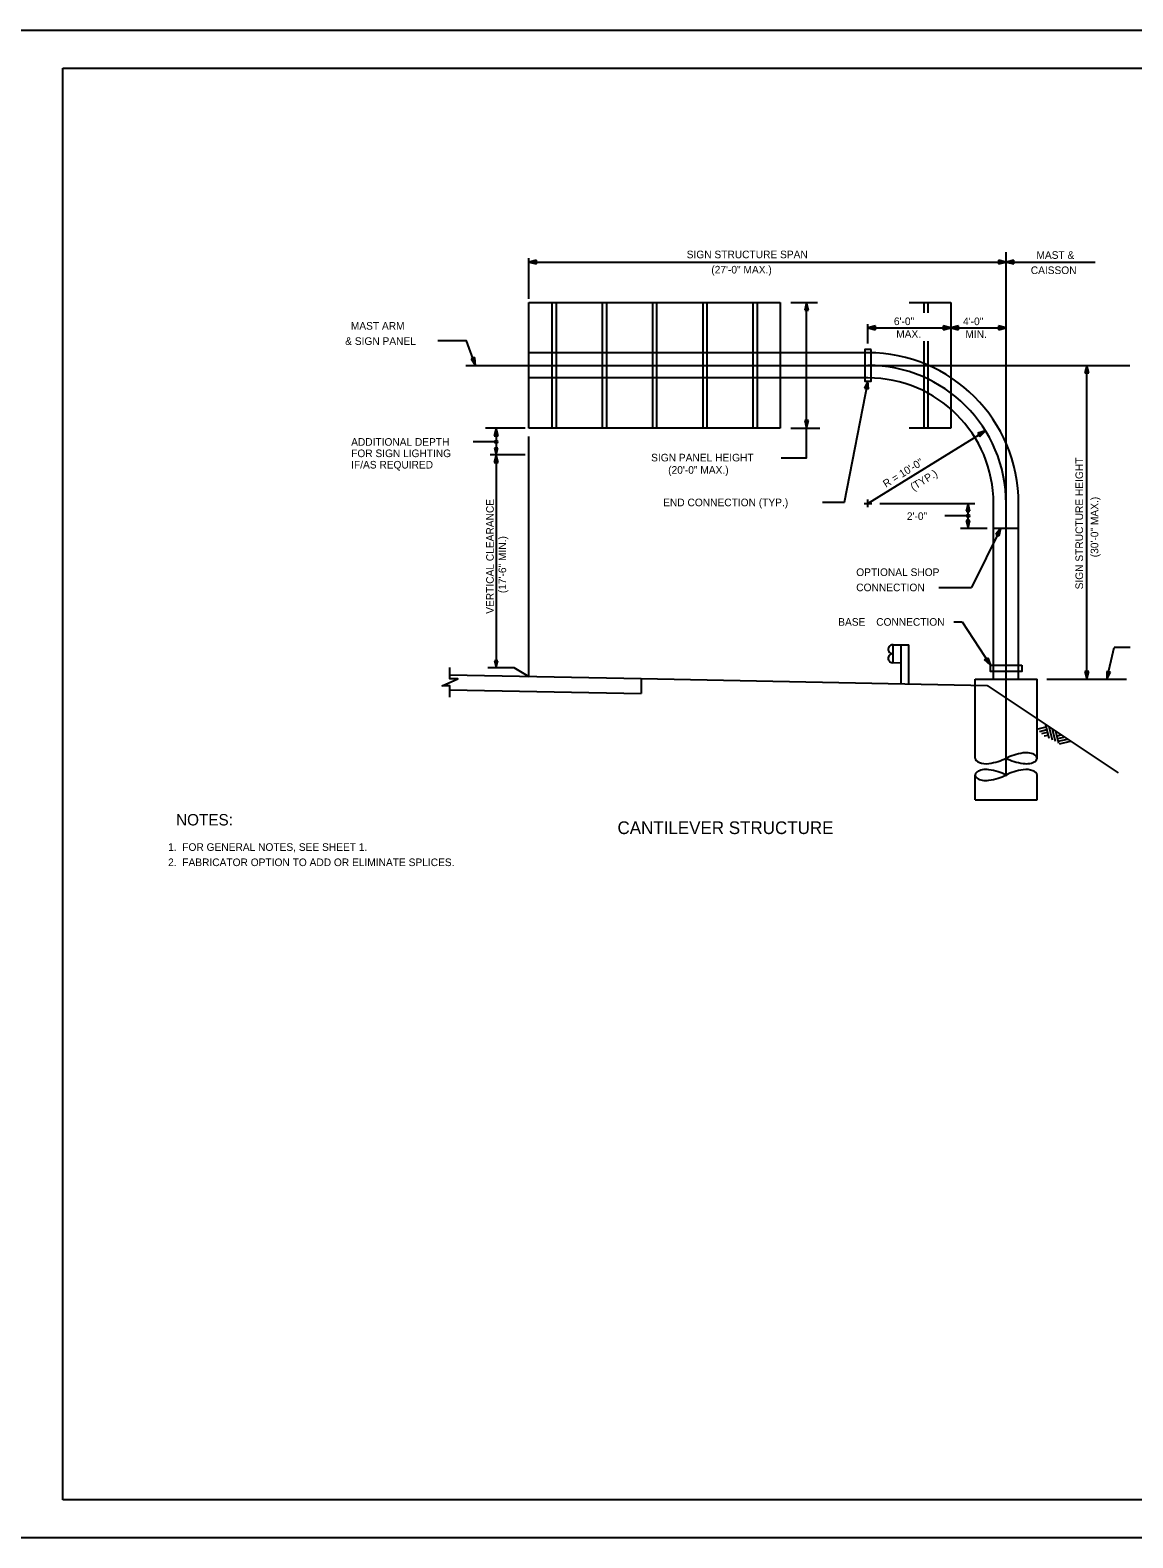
# Model space of a CAD drawing. Extents: x 640117 to 642655, y 297247 to 298435.
# Drawn here: x 641827 to 642261, y 297841 to 298435 of the extents above; entities that cross this region are included whole.
import ezdxf

# ---------------------------------------------------------------- set-up
doc = ezdxf.new("R2010")
doc.units = 0
for name, color, linetype in [('10', 7, 'Continuous'), ('2', 7, 'Continuous'), ('25', 7, 'Continuous'), ('46', 7, 'Continuous'), ('47', 7, 'Continuous'), ('49', 7, 'Continuous'), ('50', 7, 'Continuous'), ('51', 7, 'Continuous'), ('52', 7, 'Continuous'), ('53', 7, 'Continuous'), ('55', 7, 'Continuous'), ('56', 7, 'Continuous'), ('PLT-BNDY', 7, 'Continuous')]:
    doc.layers.add(name, color=color, linetype=linetype)

msp = doc.modelspace()

# ---------------------------------------------------------------- linework, layer by layer
at = {"layer": '10'}
for p, q in [((642126.25, 298328.13), (642136.71, 298328.13)), ((642001.67, 298306.51), (642000.24, 298306)), ((642000.24, 298306), (642001.99, 298303.4)), ((642001.52, 298306.27), (642000.52, 298305.91)), ((642000.52, 298305.91), (642001.74, 298304.1)), ((642001.36, 298306.02), (642000.8, 298305.82)), ((642000.8, 298305.82), (642001.49, 298304.79)), ((642001.02, 298305.82), (642001.23, 298305.49)), ((642001.23, 298305.49), (642001.2, 298305.86)), ((642001.49, 298304.79), (642001.36, 298306.02)), ((642001.74, 298304.1), (642001.52, 298306.27)), ((642001.99, 298303.4), (642001.67, 298306.51)), ((642010.12, 298278.66), (642010.12, 298184.29)), ((642126.25, 298278.66), (642137.62, 298278.66)), ((642009.46, 298270.82), (642010.12, 298268.18)), ((642010.78, 298270.82), (642009.46, 298270.82)), ((642009.66, 298270.66), (642010.12, 298268.82)), ((642010.58, 298270.66), (642009.66, 298270.66)), ((642009.86, 298270.51), (642010.12, 298269.47)), ((642010.38, 298270.51), (642009.86, 298270.51)), ((642010.04, 298270.44), (642010.12, 298270.12)), ((642010.12, 298268.18), (642010.78, 298270.82)), ((642010.12, 298268.82), (642010.58, 298270.66)), ((642010.12, 298269.47), (642010.38, 298270.51)), ((642010.12, 298270.12), (642010.2, 298270.43)), ((642009.46, 298186.93), (642010.12, 298184.29)), ((642010.78, 298186.93), (642009.46, 298186.93)), ((642009.66, 298186.78), (642010.12, 298184.93)), ((642010.58, 298186.78), (642009.66, 298186.78)), ((642009.86, 298186.62), (642010.12, 298185.58)), ((642010.38, 298186.62), (642009.86, 298186.62)), ((642010.04, 298186.56), (642010.12, 298186.23)), ((642010.12, 298184.29), (642010.78, 298186.93)), ((642010.12, 298184.93), (642010.58, 298186.78)), ((642010.12, 298185.58), (642010.38, 298186.62)), ((642010.12, 298186.23), (642010.2, 298186.54))]:
    msp.add_line(p, q, dxfattribs=at)
for points in [[(642001.99, 298303.4), (641998.5, 298313.07), (641987.09, 298313.07)], [(642006.86, 298184.29), (642017.06, 298184.29), (642022.99, 298180.86)]]:
    msp.add_lwpolyline(points, dxfattribs=at)
at = {"layer": '2'}
for p, q in [((641839.46, 297856.46), (641839.46, 298420.46)), ((641839.46, 298420.46), (642625.46, 298420.46)), ((642625.46, 297856.46), (641839.46, 297856.46))]:
    msp.add_line(p, q, dxfattribs=at)
at = {"layer": '25'}
for p, q in [((641991.93, 298181.48), (642067.18, 298179.98)), ((642067.18, 298179.98), (642067.18, 298174.07))]:
    msp.add_line(p, q, dxfattribs=at)
msp.add_lwpolyline([(641991.93, 298175.57), (642067.18, 298174.07)], dxfattribs=at)
at = {"layer": '46'}
for p, q in [((642166.5, 298193.29), (642172.69, 298193.29)), ((642166.5, 298186.26), (642166.5, 298193.29)), ((642169.59, 298177.93), (642169.59, 298193.29)), ((642172.69, 298177.87), (642172.69, 298193.29)), ((642166.06, 298186.26), (642169.62, 298186.24))]:
    msp.add_line(p, q, dxfattribs=at)
for centre in [(642166.27, 298188.01), (642166.29, 298191.54)]:
    msp.add_arc(centre, 1.76, 83.03516, 270.41141, dxfattribs=at)
at = {"layer": '47'}
for p, q in [((642067.18, 298179.98), (642203.55, 298177.25)), ((642203.55, 298177.25), (642255.07, 298142.91))]:
    msp.add_line(p, q, dxfattribs=at)
at = {"layer": '49'}
for p, q in [((642022.99, 298328.13), (642121.93, 298328.13)), ((642022.99, 298278.66), (642022.99, 298328.13)), ((642032.11, 298328.13), (642032.11, 298278.66)), ((642033.76, 298328.13), (642033.76, 298278.66)), ((642051.9, 298328.13), (642051.9, 298278.66)), ((642053.55, 298328.13), (642053.55, 298278.66)), ((642071.69, 298328.13), (642071.69, 298278.66)), ((642073.34, 298328.13), (642073.34, 298278.66)), ((642091.48, 298328.13), (642091.48, 298278.66)), ((642093.13, 298328.13), (642093.13, 298278.66)), ((642111.26, 298328.13), (642111.26, 298278.66)), ((642112.91, 298328.13), (642112.91, 298278.66)), ((642121.93, 298328.13), (642121.93, 298278.66)), ((642172.78, 298328.13), (642189.21, 298328.13)), ((642178.54, 298328.13), (642178.54, 298324.03)), ((642180.19, 298328.13), (642180.19, 298324.03)), ((642189.21, 298328.13), (642189.21, 298278.66)), ((642178.54, 298312.94), (642178.54, 298278.66)), ((642180.19, 298312.94), (642180.19, 298278.66)), ((642121.93, 298278.66), (642022.99, 298278.66)), ((642189.21, 298278.66), (642172.78, 298278.66))]:
    msp.add_line(p, q, dxfattribs=at)
at = {"layer": '50'}
for p, q in [((642210.98, 298141.48), (642210.98, 298347.96)), ((641998.24, 298303.4), (642259.74, 298303.4))]:
    msp.add_line(p, q, dxfattribs=at)
msp.add_arc((642156.56, 298248.98), 54.42, 0, 89.99967, dxfattribs=at)
at = {"layer": '51'}
for p, q in [((642198.78, 298179.72), (642223.17, 298179.72)), ((642198.78, 298177.34), (642198.78, 298179.72)), ((642198.78, 298148.62), (642198.78, 298177.34)), ((642223.17, 298164.17), (642223.17, 298179.72)), ((642223.17, 298148.62), (642223.17, 298164.17)), ((642198.78, 298132.22), (642198.78, 298141.99)), ((642223.17, 298132.22), (642223.17, 298141.99)), ((642198.78, 298132.22), (642223.17, 298132.22))]:
    msp.add_line(p, q, dxfattribs=at)
for centre, major_axis, start_param, end_param in [((642203.1, 298148.62), (-4.32, 0), 0, 1.827597), ((642198.78, 298154.71), (-17.24, 0), 1.89032, 2.356194), ((642223.17, 298142.52), (17.24, 0), 1.89032, 2.356194), ((642223.17, 298154.71), (17.24, 0), 3.926991, 4.392865), ((642218.85, 298148.62), (4.32, 0), 4.455588, 8.110783), ((642203.1, 298141.99), (-4.32, 0), 4.455588, 8.110783), ((642198.78, 298135.9), (-17.24, 0), 3.926991, 4.392865), ((642198.78, 298148.09), (-17.24, 0), 1.89032, 2.356194), ((642223.17, 298135.9), (17.24, 0), 1.89032, 2.356194), ((642218.85, 298141.99), (4.32, 0), 0, 1.827597)]:
    msp.add_ellipse(centre, major_axis=major_axis, ratio=0.5, start_param=start_param, end_param=end_param, dxfattribs=at)
at = {"layer": '52'}
for p, q in [((642022.99, 298329.63), (642022.99, 298345.59)), ((642025.99, 298344.84), (642022.99, 298344.09)), ((642022.99, 298344.09), (642210.98, 298344.09)), ((642022.99, 298344.09), (642025.99, 298343.34)), ((642025.81, 298344.61), (642023.72, 298344.09)), ((642023.72, 298344.09), (642025.81, 298343.57)), ((642025.63, 298344.39), (642024.45, 298344.09)), ((642024.45, 298344.09), (642025.63, 298343.8)), ((642025.56, 298344.18), (642025.19, 298344.09)), ((642025.19, 298344.09), (642025.54, 298344)), ((642025.63, 298343.8), (642025.63, 298344.39)), ((642025.81, 298343.57), (642025.81, 298344.61)), ((642025.99, 298343.34), (642025.99, 298344.84)), ((642210.98, 298344.09), (642207.98, 298344.84)), ((642207.98, 298344.84), (642207.98, 298343.34)), ((642207.98, 298343.34), (642210.98, 298344.09)), ((642210.24, 298344.09), (642208.15, 298344.61)), ((642208.15, 298344.61), (642208.15, 298343.57)), ((642208.15, 298343.57), (642210.24, 298344.09)), ((642209.51, 298344.09), (642208.33, 298344.39)), ((642208.33, 298344.39), (642208.33, 298343.8)), ((642208.33, 298343.8), (642209.51, 298344.09)), ((642208.4, 298344), (642208.78, 298344.09)), ((642208.78, 298344.09), (642208.42, 298344.18)), ((642213.98, 298344.84), (642210.98, 298344.09)), ((642210.98, 298344.09), (642213.98, 298343.34)), ((642213.8, 298344.61), (642211.71, 298344.09)), ((642211.71, 298344.09), (642213.8, 298343.57)), ((642213.62, 298344.39), (642212.44, 298344.09)), ((642212.44, 298344.09), (642213.62, 298343.8)), ((642213.55, 298344.18), (642213.17, 298344.09)), ((642213.17, 298344.09), (642213.53, 298344)), ((642213.62, 298343.8), (642213.62, 298344.39)), ((642213.8, 298343.57), (642213.8, 298344.61)), ((642213.98, 298343.34), (642213.98, 298344.84)), ((642132.4, 298328.13), (642131.66, 298325.13)), ((642131.66, 298325.13), (642133.15, 298325.13)), ((642132.4, 298327.4), (642131.88, 298325.31)), ((642131.88, 298325.31), (642132.93, 298325.31)), ((642132.4, 298326.67), (642132.11, 298325.49)), ((642132.11, 298325.49), (642132.7, 298325.49)), ((642132.4, 298325.93), (642132.32, 298325.58)), ((642133.15, 298325.13), (642132.4, 298328.13)), ((642132.93, 298325.31), (642132.4, 298327.4)), ((642132.7, 298325.49), (642132.4, 298326.67)), ((642132.5, 298325.56), (642132.4, 298325.93)), ((642156.56, 298311.96), (642156.56, 298319.65)), ((642159.56, 298318.93), (642156.56, 298318.18)), ((642159.38, 298318.71), (642157.29, 298318.18)), ((642159.38, 298317.66), (642159.38, 298318.71)), ((642159.56, 298317.43), (642159.56, 298318.93)), ((642189.21, 298318.18), (642186.21, 298318.93)), ((642186.21, 298318.93), (642186.21, 298317.43)), ((642188.48, 298318.18), (642186.39, 298318.71)), ((642186.39, 298318.71), (642186.39, 298317.66)), ((642192.21, 298318.93), (642189.21, 298318.18)), ((642192.03, 298318.71), (642189.94, 298318.18)), ((642192.03, 298317.66), (642192.03, 298318.71)), ((642192.21, 298317.43), (642192.21, 298318.93)), ((642210.98, 298318.18), (642207.98, 298318.93)), ((642207.98, 298318.93), (642207.98, 298317.43)), ((642210.24, 298318.18), (642208.15, 298318.71)), ((642208.15, 298318.71), (642208.15, 298317.66)), ((642156.56, 298318.18), (642189.21, 298318.18)), ((642156.56, 298318.18), (642159.56, 298317.43)), ((642157.29, 298318.18), (642159.38, 298317.66)), ((642159.2, 298318.48), (642158.02, 298318.18)), ((642158.02, 298318.18), (642159.2, 298317.89)), ((642159.13, 298318.28), (642158.76, 298318.18)), ((642158.76, 298318.18), (642159.11, 298318.09)), ((642159.2, 298317.89), (642159.2, 298318.48)), ((642186.21, 298317.43), (642189.21, 298318.18)), ((642186.39, 298317.66), (642188.48, 298318.18)), ((642187.74, 298318.18), (642186.56, 298318.48)), ((642186.56, 298318.48), (642186.56, 298317.89)), ((642186.56, 298317.89), (642187.74, 298318.18)), ((642186.63, 298318.09), (642187.01, 298318.18)), ((642187.01, 298318.18), (642186.65, 298318.27)), ((642189.21, 298318.18), (642210.98, 298318.18)), ((642189.21, 298318.18), (642192.21, 298317.43)), ((642189.94, 298318.18), (642192.03, 298317.66)), ((642191.85, 298318.48), (642190.67, 298318.18)), ((642190.67, 298318.18), (642191.85, 298317.89)), ((642191.78, 298318.28), (642191.41, 298318.18)), ((642191.41, 298318.18), (642191.76, 298318.09)), ((642191.85, 298317.89), (642191.85, 298318.48)), ((642207.98, 298317.43), (642210.98, 298318.18)), ((642208.15, 298317.66), (642210.24, 298318.18)), ((642209.51, 298318.18), (642208.33, 298318.48)), ((642208.33, 298318.48), (642208.33, 298317.89)), ((642208.33, 298317.89), (642209.51, 298318.18)), ((642208.4, 298318.09), (642208.78, 298318.18)), ((642208.78, 298318.18), (642208.42, 298318.27)), ((642242.79, 298303.4), (642242.04, 298300.4)), ((642242.79, 298302.66), (642242.27, 298300.57)), ((642242.79, 298301.93), (642242.49, 298300.75)), ((642242.79, 298301.2), (642242.7, 298300.84)), ((642242.79, 298179.72), (642242.79, 298303.4)), ((642243.54, 298300.4), (642242.79, 298303.4)), ((642243.31, 298300.57), (642242.79, 298302.66)), ((642243.09, 298300.75), (642242.79, 298301.93)), ((642242.88, 298300.82), (642242.79, 298301.2)), ((642156.56, 298297.21), (642155.25, 298294.41)), ((642156.42, 298296.49), (642155.5, 298294.54)), ((642156.28, 298295.78), (642155.76, 298294.67)), ((642156.14, 298295.06), (642155.98, 298294.72)), ((642156.15, 298294.67), (642156.14, 298295.06)), ((642156.34, 298294.56), (642156.28, 298295.78)), ((642156.53, 298294.34), (642156.42, 298296.49)), ((642156.72, 298294.13), (642156.56, 298297.21)), ((642242.04, 298300.4), (642243.54, 298300.4)), ((642242.27, 298300.57), (642243.31, 298300.57)), ((642242.49, 298300.75), (642243.09, 298300.75)), ((642155.25, 298294.41), (642156.72, 298294.13)), ((642155.5, 298294.54), (642156.53, 298294.34)), ((642155.76, 298294.67), (642156.34, 298294.56)), ((642021.49, 298278.66), (642005.96, 298278.66)), ((642010.12, 298278.66), (642009.37, 298275.66)), ((642010.12, 298277.93), (642009.6, 298275.84)), ((642010.12, 298277.2), (642009.82, 298276.02)), ((642010.87, 298275.66), (642010.12, 298278.66)), ((642010.64, 298275.84), (642010.12, 298277.93)), ((642010.42, 298276.02), (642010.12, 298277.2)), ((642131.66, 298281.66), (642132.4, 298278.66)), ((642133.15, 298281.66), (642131.66, 298281.66)), ((642131.88, 298281.49), (642132.4, 298279.4)), ((642132.93, 298281.49), (642131.88, 298281.49)), ((642132.11, 298281.31), (642132.4, 298280.13)), ((642132.7, 298281.31), (642132.11, 298281.31)), ((642132.31, 298281.24), (642132.4, 298280.86)), ((642132.4, 298278.66), (642133.15, 298281.66)), ((642132.4, 298279.4), (642132.93, 298281.49)), ((642132.4, 298280.13), (642132.7, 298281.31)), ((642132.4, 298280.86), (642132.49, 298281.22)), ((642156.56, 298248.98), (642202.83, 298277.62)), ((642202.83, 298277.62), (642199.88, 298276.68)), ((642202.21, 298277.23), (642200.15, 298276.58)), ((642200.67, 298275.4), (642202.83, 298277.62)), ((642200.7, 298275.69), (642202.21, 298277.23)), ((642010.12, 298273.3), (642001.03, 298273.3)), ((642009.37, 298275.66), (642010.87, 298275.66)), ((642009.6, 298275.84), (642010.64, 298275.84)), ((642009.82, 298276.02), (642010.42, 298276.02)), ((642010.12, 298276.46), (642010.03, 298276.11)), ((642010.21, 298276.09), (642010.12, 298276.46)), ((642022.99, 298180.86), (642022.99, 298275.32)), ((642199.88, 298276.68), (642200.67, 298275.4)), ((642200.15, 298276.58), (642200.7, 298275.69)), ((642201.58, 298276.85), (642200.43, 298276.48)), ((642200.43, 298276.48), (642200.74, 298275.97)), ((642200.96, 298276.46), (642200.61, 298276.35)), ((642200.69, 298276.18), (642200.96, 298276.46)), ((642200.74, 298275.97), (642201.58, 298276.85)), ((642021.49, 298268.18), (642007.8, 298268.18)), ((642010.12, 298268.18), (642009.37, 298265.18)), ((642010.12, 298267.45), (642009.6, 298265.36)), ((642009.6, 298265.36), (642010.64, 298265.36)), ((642010.12, 298266.71), (642009.82, 298265.53)), ((642009.82, 298265.53), (642010.42, 298265.53)), ((642010.12, 298265.98), (642010.03, 298265.62)), ((642010.87, 298265.18), (642010.12, 298268.18)), ((642010.64, 298265.36), (642010.12, 298267.45)), ((642010.42, 298265.53), (642010.12, 298266.71)), ((642010.21, 298265.61), (642010.12, 298265.98)), ((642009.37, 298265.18), (642010.87, 298265.18)), ((642155.06, 298248.98), (642158.06, 298248.98)), ((642156.56, 298247.48), (642156.56, 298250.48)), ((642161.23, 298248.98), (642198.61, 298248.98)), ((642195.99, 298248.98), (642195.24, 298245.98)), ((642195.99, 298248.25), (642195.46, 298246.16)), ((642195.99, 298247.51), (642195.69, 298246.33)), ((642195.99, 298239.23), (642195.99, 298248.98)), ((642196.73, 298245.98), (642195.99, 298248.98)), ((642196.51, 298246.16), (642195.99, 298248.25)), ((642196.28, 298246.33), (642195.99, 298247.51)), ((642195.99, 298244.1), (642186.89, 298244.1)), ((642195.24, 298245.98), (642196.73, 298245.98)), ((642195.24, 298242.23), (642195.99, 298239.23)), ((642196.73, 298242.23), (642195.24, 298242.23)), ((642195.46, 298246.16), (642196.51, 298246.16)), ((642195.46, 298242.05), (642195.99, 298239.96)), ((642196.51, 298242.05), (642195.46, 298242.05)), ((642195.69, 298246.33), (642196.28, 298246.33)), ((642195.69, 298241.87), (642195.99, 298240.69)), ((642196.28, 298241.87), (642195.69, 298241.87)), ((642195.89, 298241.8), (642195.99, 298241.42)), ((642195.99, 298246.78), (642195.9, 298246.42)), ((642196.08, 298246.41), (642195.99, 298246.78)), ((642195.99, 298239.23), (642196.73, 298242.23)), ((642195.99, 298239.96), (642196.51, 298242.05)), ((642195.99, 298240.69), (642196.28, 298241.87)), ((642195.99, 298241.42), (642196.08, 298241.78)), ((642193.08, 298239.23), (642203.49, 298239.23)), ((642208.91, 298239.23), (642206.91, 298236.87)), ((642206.91, 298236.87), (642208.25, 298236.21)), ((642208.59, 298238.57), (642207.19, 298236.93)), ((642207.19, 298236.93), (642208.13, 298236.47)), ((642208.26, 298237.91), (642207.47, 298236.99)), ((642207.47, 298236.99), (642208, 298236.73)), ((642207.94, 298237.26), (642207.7, 298236.98)), ((642207.85, 298236.88), (642207.94, 298237.26)), ((642208, 298236.73), (642208.26, 298237.91)), ((642208.13, 298236.47), (642208.59, 298238.57)), ((642208.25, 298236.21), (642208.91, 298239.23)), ((642184.44, 298215.84), (642197.32, 298215.84)), ((642190.34, 298202.36), (642193.62, 298202.36)), ((642193.62, 298202.36), (642204.79, 298185.26)), ((642202.52, 298187.36), (642203.78, 298188.18)), ((642203.78, 298188.18), (642204.79, 298185.26)), ((642259.9, 298192.27), (642253.56, 298192.27)), ((642204.79, 298185.26), (642202.52, 298187.36)), ((642202.81, 298187.33), (642203.69, 298187.91)), ((642204.39, 298185.87), (642202.81, 298187.33)), ((642203.1, 298187.31), (642203.59, 298187.63)), ((642203.99, 298186.48), (642203.1, 298187.31)), ((642203.59, 298187.1), (642203.32, 298187.35)), ((642203.46, 298187.46), (642203.59, 298187.1)), ((642203.59, 298187.63), (642203.99, 298186.48)), ((642203.69, 298187.91), (642204.39, 298185.87)), ((642242.04, 298182.72), (642242.79, 298179.72)), ((642243.54, 298182.72), (642242.04, 298182.72)), ((642242.27, 298182.54), (642242.79, 298180.45)), ((642243.31, 298182.54), (642242.27, 298182.54)), ((642242.49, 298182.37), (642242.79, 298181.19)), ((642243.09, 298182.37), (642242.49, 298182.37)), ((642242.7, 298182.3), (642242.79, 298181.92)), ((642242.79, 298179.72), (642243.54, 298182.72)), ((642242.79, 298180.45), (642243.31, 298182.54)), ((642242.79, 298181.19), (642243.09, 298182.37)), ((642242.79, 298181.92), (642242.88, 298182.28)), ((642250.61, 298182.81), (642250.66, 298179.72)), ((642252.07, 298182.48), (642250.61, 298182.81)), ((642250.66, 298179.72), (642252.07, 298182.48)), ((642250.79, 298182.59), (642250.83, 298180.44)), ((642251.81, 298182.35), (642250.79, 298182.59)), ((642250.83, 298180.44), (642251.81, 298182.35)), ((642250.97, 298182.37), (642250.99, 298181.15)), ((642251.55, 298182.23), (642250.97, 298182.37)), ((642250.99, 298181.15), (642251.55, 298182.23)), ((642251.15, 298182.25), (642251.16, 298181.86)), ((642251.16, 298181.86), (642251.32, 298182.19)), ((642227.05, 298179.72), (642258.38, 298179.72))]:
    msp.add_line(p, q, dxfattribs=at)
for points in [[(642210.98, 298344.09), (642246.09, 298344.09)], [(642122.37, 298266.9), (642132.4, 298266.9), (642132.4, 298328.13)], [(642156.56, 298297.21), (642147.13, 298249.38), (642138.62, 298249.38)], [(642208.91, 298239.23), (642197.32, 298215.84)], [(642250.66, 298179.72), (642253.56, 298192.27)], [(641991.93, 298172.69), (641991.93, 298177.18), (641988.81, 298177.18), (641995.05, 298179.87), (641991.93, 298179.87), (641991.93, 298184.36)]]:
    msp.add_lwpolyline(points, dxfattribs=at)
for centre, radius in [((642010.12, 298273.3), 0.536), ((642010.12, 298273.3), 0.268), ((642195.99, 298244.1), 0.536), ((642195.99, 298244.1), 0.268)]:
    msp.add_circle(centre, radius, dxfattribs=at)
at = {"layer": '55'}
for p, q in [((642121.93, 298308.34), (642022.99, 298308.34)), ((642156.56, 298308.34), (642121.93, 298308.34)), ((642121.93, 298298.45), (642022.99, 298298.45)), ((642156.56, 298298.45), (642121.93, 298298.45)), ((642206.03, 298179.72), (642206.03, 298248.98)), ((642215.92, 298179.72), (642215.92, 298248.98)), ((642206.03, 298239.23), (642215.92, 298239.23))]:
    msp.add_line(p, q, dxfattribs=at)
for points in [[(642157.79, 298309.58), (642155.32, 298309.58), (642155.32, 298297.21), (642157.79, 298297.21)], [(642217.16, 298185.26), (642217.16, 298182.78), (642204.79, 298182.78), (642204.79, 298185.26)]]:
    msp.add_lwpolyline(points, close=True, dxfattribs=at)
for radius in [59.36, 49.47]:
    msp.add_arc((642156.56, 298248.98), radius, 0, 90, dxfattribs=at)
at = {"layer": '56'}
for p, q in [((642223.63, 298160.21), (642226.82, 298160.96)), ((642224.07, 298159.17), (642227.07, 298159.9)), ((642225.08, 298158.29), (642227.33, 298158.83)), ((642227.9, 298156.44), (642226.62, 298161.79)), ((642229.19, 298155.75), (642227.93, 298161.03)), ((642230.46, 298155.16), (642229.28, 298160.11)), ((642231.77, 298154.39), (642230.63, 298159.2)), ((642225.99, 298157.37), (642227.58, 298157.76)), ((642231.05, 298157.45), (642232.6, 298157.82)), ((642231.3, 298156.38), (642233.69, 298156.95)), ((642231.55, 298155.31), (642235.13, 298156.16)), ((642231.99, 298154.28), (642236.29, 298155.31))]:
    msp.add_line(p, q, dxfattribs=at)
at = {"layer": 'PLT-BNDY'}
msp.add_lwpolyline([(641799.46, 298435.46), (642640.46, 298435.46), (642640.46, 297841.46), (641799.46, 297841.46)], close=True, dxfattribs=at)

# ---------------------------------------------------------------- texts
at = {"layer": '10'}
for s, height, p in [('  MAST &', 2.992, (642220.71, 298345.36)), ('CAISSON', 2.992, (642220.71, 298339.37)), ('ADDITIONAL DEPTH', 2.9917, (641953.02, 298271.73)), ('FOR SIGN LIGHTING', 2.9917, (641953.02, 298267.24)), ('IF/AS REQUIRED', 2.9917, (641953.02, 298262.75)), ('BASE ', 2.992, (642144.87, 298200.81)), ('CONNECTION', 2.992, (642159.83, 298200.81)), ('NOTES:', 4.5, (641884.04, 298122.12))]:
    msp.add_text(s, height=height, dxfattribs=at).set_placement(p)
at = {"layer": '2'}
for s, p in [('SIGN PANEL HEIGHT', (642071.16, 298265.55)), ('(20\'-0" MAX.)', (642077.87, 298260.68))]:
    msp.add_text(s, height=3, dxfattribs=at).set_placement(p)
for s, rotation, p in [('R = 10\'-0"', 31.75343, (642163.64, 298255.12)), ('SIGN STRUCTURE HEIGHT', 90, (642241.29, 298215.13)), ('(TYP.)', 31.75343, (642174.44, 298253.88)), ('(30\'-0" MAX.)', 90, (642247.29, 298227.79)), ('2\'-0"', 360, (642171.89, 298242.47)), ('OPTIONAL SHOP', 360, (642151.95, 298220.4)), ('CONNECTION', 360, (642151.95, 298214.4))]:
    msp.add_text(s, height=3, rotation=rotation, dxfattribs=at).set_placement(p)
at = {"layer": '52'}
for s, p in [('SIGN STRUCTURE SPAN', (642085.17, 298345.59)), ('(27\'-0" MAX.)', (642094.86, 298339.59)), ('6\'-0"', (642166.78, 298319.25)), ('4\'-0"', (642194.02, 298319.23))]:
    msp.add_text(s, height=3, dxfattribs=at).set_placement(p)
at = {"layer": '53'}
for s, height, p in [('  MAST ARM', 3, (641950.65, 298317.45)), ('& SIGN PANEL', 3, (641950.65, 298311.45)), ('MAX.', 3, (642167.69, 298314.25)), ('MIN.', 3, (642194.93, 298314.23)), ('END CONNECTION (TYP.)', 3, (642075.9, 298247.88)), ('CANTILEVER STRUCTURE', 5, (642057.91, 298118.73)), ('1.  FOR GENERAL NOTES, SEE SHEET 1.', 3, (641880.91, 298112.11)), ('2.  FABRICATOR OPTION TO ADD OR ELIMINATE SPLICES.', 3, (641880.91, 298106.11))]:
    msp.add_text(s, height=height, dxfattribs=at).set_placement(p)
for s, p in [('VERTICAL CLEARANCE', (642009.18, 298205.52)), ('(17\'-6" MIN.)', (642014.06, 298213.65))]:
    msp.add_text(s, height=3, rotation=90, dxfattribs=at).set_placement(p)

doc.saveas('drawing.dxf')
